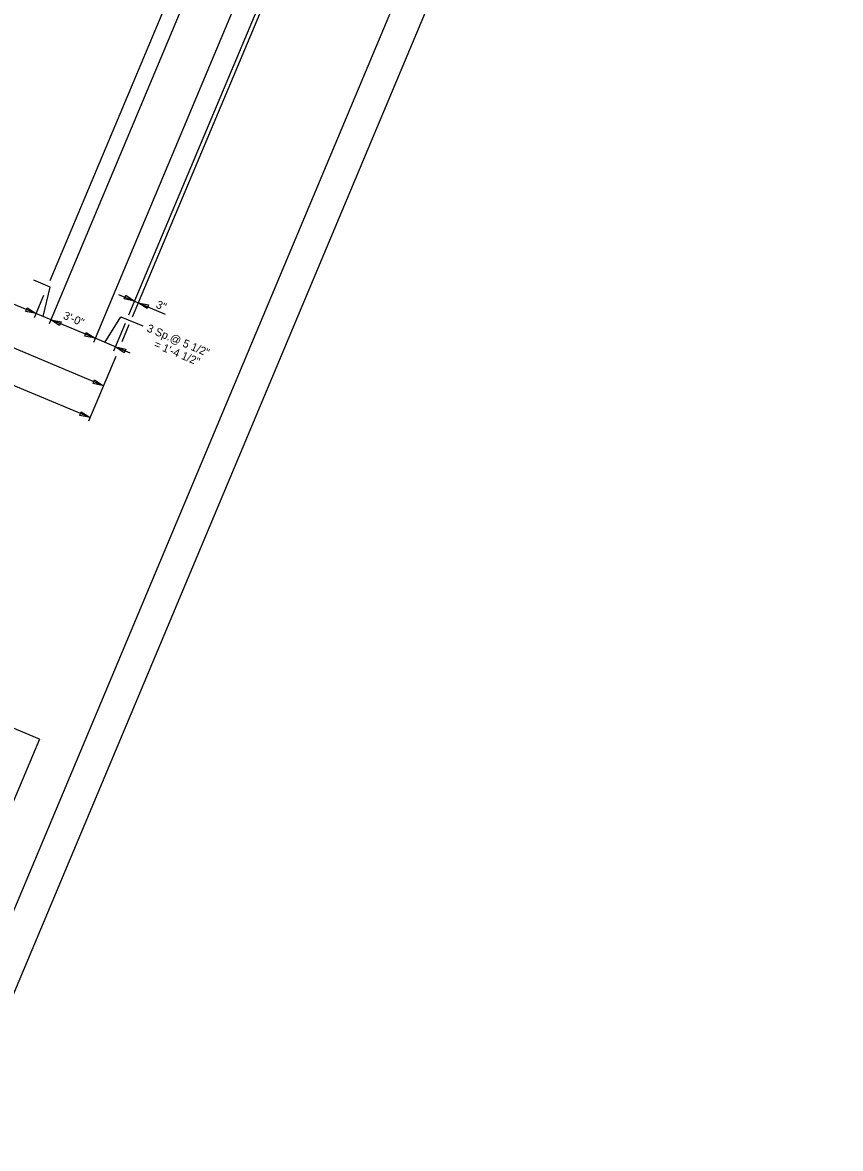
# Model space of a CAD drawing. Extents: x 1968564 to 1968701, y 796599 to 796766.
# Drawn here: x 1968649.6 to 1968700.7, y 796598.9 to 796669.3 of the extents above; entities that cross this region are included whole.
import ezdxf

# ---------------------------------------------------------------- set-up
doc = ezdxf.new("R2010")
doc.units = 0
for name, color, linetype in [('BR_AUTO DIMENSION', 7, 'Continuous'), ('BR_BORDER LINES', 7, 'Continuous'), ('Level 31', 7, 'Continuous')]:
    doc.layers.add(name, color=color, linetype=linetype)

msp = doc.modelspace()

# ---------------------------------------------------------------- linework, layer by layer
at = {"layer": 'BR_AUTO DIMENSION'}
for p, q in [((1968670.518, 796698.902), (1968651.312, 796653.111)), ((1968675.7, 796696.716), (1968656.465, 796650.854)), ((1968666.888, 796687.664), (1968651.27, 796650.425)), ((1968669.655, 796686.504), (1968654.729, 796650.915)), ((1968670.942, 796686.017), (1968656.24, 796650.963)), ((1968654.146, 796649.526), (1968601.582, 796671.573)), ((1968653.831, 796644.573), (1968598.27, 796667.876)), ((1968654.666, 796646.564), (1968620.43, 796660.923)), ((1968651.341, 796652.729), (1968650.31, 796653.162)), ((1968650.894, 796650.89), (1968651.341, 796652.729)), ((1968650.932, 796652.204), (1968650.348, 796650.812)), ((1968655.598, 796652.273), (1968658.529, 796651.043)), ((1968654.729, 796650.915), (1968654.037, 796649.265)), ((1968654.757, 796649.27), (1968655.755, 796650.878)), ((1968655.755, 796650.878), (1968657.134, 796650.299)), ((1968656.029, 796650.46), (1968655.304, 796648.733)), ((1968656.259, 796650.364), (1968655.818, 796649.311)), ((1968656.339, 796648.606), (1968654.146, 796649.526)), ((1968655.436, 796648.401), (1968653.734, 796644.342))]:
    msp.add_line(p, q, dxfattribs=at)
for points in [[(1968656.06, 796652.215), (1968656.611, 796651.848), (1968655.963, 796651.984)], [(1968649.906, 796651.44), (1968650.457, 796651.073), (1968649.81, 796651.21)], [(1968657.392, 796651.385), (1968656.841, 796651.751), (1968657.489, 796651.615)], [(1968651.931, 796650.32), (1968651.38, 796650.687), (1968652.027, 796650.551)], [(1968653.595, 796649.893), (1968654.146, 796649.526), (1968653.498, 796649.662)], [(1968655.965, 796648.628), (1968655.414, 796648.995), (1968656.062, 796648.858)], [(1968654.115, 796646.93), (1968654.666, 796646.564), (1968654.018, 796646.7)], [(1968653.28, 796644.94), (1968653.831, 796644.573), (1968653.183, 796644.709)]]:
    msp.add_lwpolyline(points, close=True, dxfattribs=at)
at = {"layer": 'BR_BORDER LINES'}
for p, q in [((1968643.927, 796601.539), (1968696.012, 796725.723)), ((1968650.664, 796624.496), (1968606.421, 796643.052)), ((1968650.664, 796624.496), (1968641.519, 796602.691))]:
    msp.add_line(p, q, dxfattribs=at)
at = {"layer": 'Level 31'}
msp.add_lwpolyline([(1968619.541, 796765.748), (1968563.846, 796632.955), (1968644.997, 796598.919), (1968700.693, 796731.712)], close=True, dxfattribs=at)

# ---------------------------------------------------------------- texts
at = {"layer": 'BR_AUTO DIMENSION'}
for s, height, p in [('3"', 0.5, (1968657.904, 796651.456)), ('3\'-0"', 0.5, (1968652.108, 796650.77)), ('3 Sp.@ 5 1/2" ', 0.49995, (1968657.329, 796649.972)), ('= 1\'-4 1/2"', 0.49995, (1968657.771, 796648.974))]:
    msp.add_text(s, height=height, rotation=337.24601, dxfattribs=at).set_placement(p)

doc.saveas('drawing.dxf')
